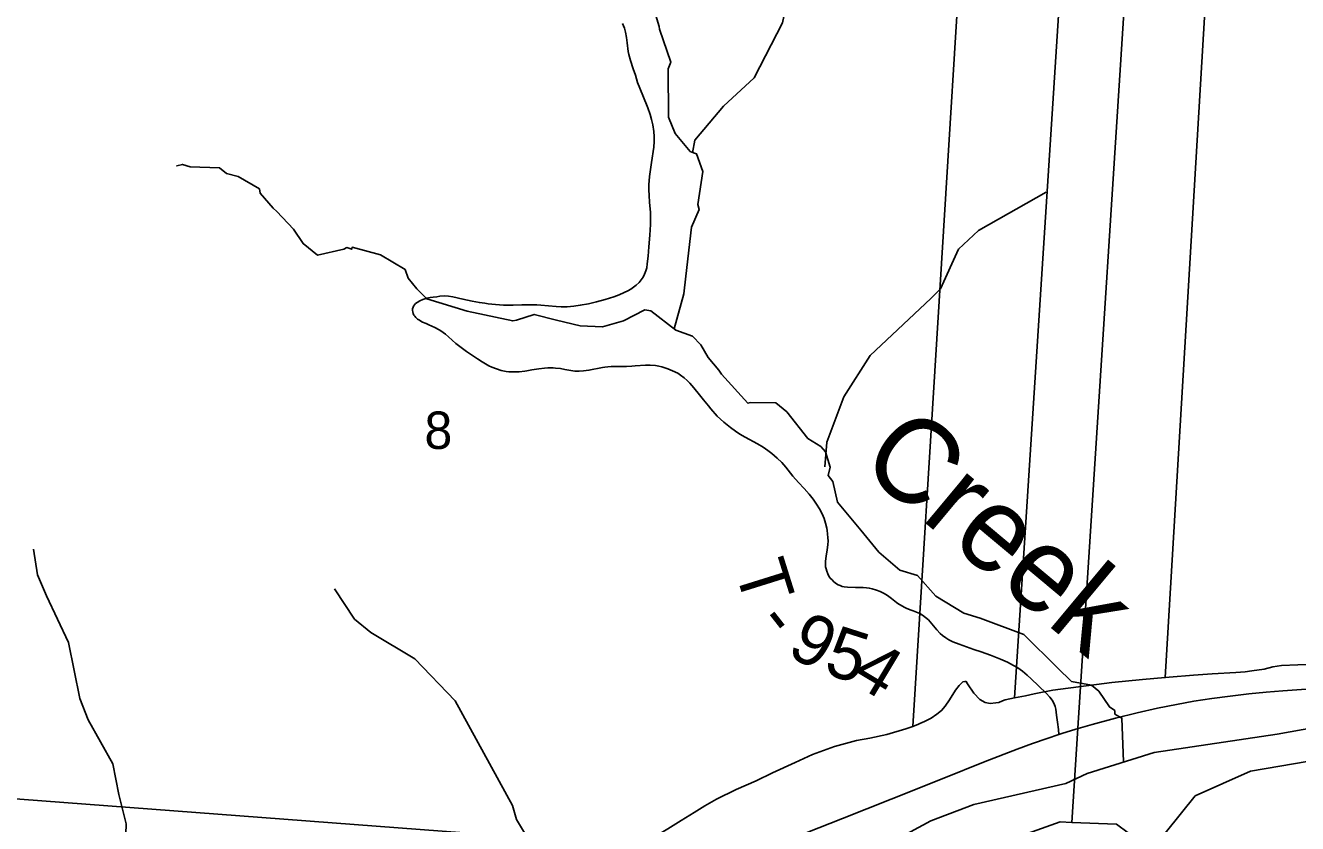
# Model space of a CAD drawing. Extents: x 0 to 34, y 0 to 22.
# Drawn here: x 27.11 to 28.533, y 15.294 to 16.186 of the extents above; entities that cross this region are included whole.
import ezdxf

# ---------------------------------------------------------------- set-up
doc = ezdxf.new("R2010")
doc.units = 0
for name, color, linetype in [('GM_X_County_Text', 7, 'Continuous'), ('GM_X_Major_River', 7, 'Continuous'), ('GM_X_Minor_River', 7, 'Continuous'), ('GM_X_Minor_River_Text', 7, 'Continuous'), ('GM_X_Section', 7, 'Continuous'), ('GM_X_Section_Text', 7, 'Continuous'), ('GM_X_State_Route', 7, 'Continuous'), ('GM_X_Township_Road', 7, 'Continuous'), ('GM_X_Township_Road_Text', 7, 'Continuous'), ('SH_Cut_Line', 7, 'Continuous')]:
    doc.layers.add(name, color=color, linetype=linetype)

msp = doc.modelspace()

# ---------------------------------------------------------------- linework, layer by layer
at = {"layer": 'GM_X_County_Text'}
for points in [[(27.0716, 14.2873), (27.1862, 14.3829), (27.4012, 14.5633), (27.5003, 14.6738), (27.528, 14.7368), (27.5892, 14.8006), (27.6689, 14.9115), (27.8265, 15.0679), (27.967, 15.1616), (28.1376, 15.2493), (28.2671, 15.2953), (28.2799, 15.2948), (28.2867, 15.4004), (28.3527, 16.4269), (28.3944, 17.0528), (28.4159, 17.3358), (28.4427, 17.7695)], [(28.4427, 17.7695), (28.4159, 17.3358), (28.3944, 17.0528), (28.3527, 16.4269), (28.2867, 15.4004), (28.2799, 15.2948), (28.3301, 15.293), (28.3692, 15.2637), (28.4182, 15.3245), (28.4801, 15.3522), (28.6571, 15.3822), (28.9104, 15.3867), (29.0987, 15.3975), (29.1238, 15.3963), (29.3286, 15.3596), (29.3112, 15.3354), (29.211, 15.3094), (29.213, 15.295), (29.3097, 15.2479), (29.423, 15.2518), (29.4264, 15.2648), (29.4018, 15.2725), (29.4304, 15.2876), (29.5713, 15.2568)]]:
    msp.add_lwpolyline(points, dxfattribs=at)
at = {"layer": 'GM_X_Major_River'}
msp.add_line((28.3722, 15.373), (28.2973, 15.3494), dxfattribs=at)
for points in [[(29.1018, 15.4118), (28.9867, 15.4094), (28.927, 15.4195), (28.9024, 15.4184), (28.7152, 15.4124), (28.568, 15.4039), (28.5098, 15.3936), (28.3722, 15.373)], [(28.2973, 15.3494), (28.2735, 15.3383), (28.1706, 15.3147), (28.1223, 15.2965), (28.072, 15.2695)]]:
    msp.add_lwpolyline(points, dxfattribs=at)
at = {"layer": 'GM_X_Minor_River'}
for points in [[(27.8558, 16.0439), (27.8582, 16.0579), (27.8903, 16.096), (27.9249, 16.1279), (27.9566, 16.1892), (27.9633, 16.2213), (27.9793, 16.2754), (27.9853, 16.3121), (27.9977, 16.3333), (28.0012, 16.3389)], [(27.8354, 15.847), (27.8462, 15.8863), (27.8481, 15.906), (27.8548, 15.9608), (27.8631, 15.9806), (27.8616, 15.9859), (27.8672, 16.0231), (27.8604, 16.0429), (27.857, 16.044), (27.8532, 16.0452), (27.8362, 16.0653), (27.829, 16.0839), (27.8286, 16.1378), (27.8316, 16.1454), (27.8187, 16.1823), (27.8183, 16.1853), (27.8149, 16.1975)], [(27.8025, 15.8684), (27.7785, 15.8561), (27.7551, 15.8492), (27.7302, 15.8503), (27.7037, 15.8567), (27.6787, 15.8631), (27.6587, 15.8566), (27.6546, 15.8558), (27.6035, 15.8667), (27.5585, 15.8807), (27.5472, 15.8917), (27.5377, 15.9038), (27.5343, 15.9133), (27.5067, 15.9296), (27.4749, 15.9383), (27.4745, 15.936), (27.4689, 15.9379), (27.4658, 15.936), (27.4364, 15.9294), (27.4201, 15.9423), (27.4095, 15.9586), (27.3906, 15.9783), (27.3868, 15.9821), (27.372, 15.9988), (27.3713, 16.0034), (27.3475, 16.0174), (27.3346, 16.0208), (27.3267, 16.0272), (27.2938, 16.0283), (27.2851, 16.0309), (27.279, 16.0294), (27.2786, 16.0294)], [(28.0036, 15.6925), (28.0059, 15.7202), (28.0251, 15.7708), (28.0545, 15.8172), (28.1223, 15.8808), (28.1333, 15.8918), (28.1533, 15.936), (28.1756, 15.9569), (28.2513, 16)], [(27.8651, 15.8291), (27.8557, 15.8388), (27.8371, 15.8456), (27.8092, 15.8672), (27.8024, 15.8684)], [(28.3377, 15.3625), (28.3361, 15.4116), (28.3282, 15.4161), (28.3282, 15.4199), (28.3222, 15.4241), (28.3104, 15.4416), (28.3021, 15.4484), (28.2798, 15.4525), (28.2639, 15.4677), (28.2264, 15.5052), (28.1777, 15.5233), (28.1591, 15.529), (28.1281, 15.5479), (28.1073, 15.5711), (28.0876, 15.5771), (28.085, 15.5794), (28.0642, 15.5972), (28.0441, 15.6219), (28.018, 15.653), (28.0127, 15.6761), (28.0074, 15.683), (28.0097, 15.6921), (28.0044, 15.7092), (27.9994, 15.7152), (27.9847, 15.7243), (27.9612, 15.7543), (27.9491, 15.7641), (27.9208, 15.7645), (27.9177, 15.7637), (27.8882, 15.7963), (27.8852, 15.8009), (27.8731, 15.8149), (27.865, 15.8292)], [(27.1708, 15.1045), (27.1625, 15.1324), (27.1653, 15.1597), (27.1982, 15.2243), (27.2153, 15.2508), (27.2215, 15.2699), (27.2222, 15.2931), (27.2141, 15.326), (27.2073, 15.3604), (27.1796, 15.4095), (27.1705, 15.4333), (27.1577, 15.496), (27.1332, 15.5484), (27.123, 15.5719), (27.1185, 15.6005)], [(27.8078, 15.0936), (27.775, 15.1224), (27.7579, 15.1446), (27.7366, 15.1806), (27.6794, 15.2637), (27.6589, 15.2981), (27.6545, 15.3138), (27.5904, 15.4309), (27.545, 15.4779), (27.496, 15.5072), (27.4775, 15.5222), (27.4551, 15.556)]]:
    msp.add_lwpolyline(points, dxfattribs=at)
at = {"layer": 'GM_X_Section'}
for points in [[(27.1082, 16.21), (27.1198, 16.4014), (27.6098, 16.3785), (28.1612, 16.354), (28.1022, 15.4021), (28.0942, 15.3994), (28.073, 15.3933), (28.0541, 15.3891), (28.0393, 15.3864), (28.0147, 15.3799), (27.9901, 15.3708), (27.9704, 15.362), (27.9454, 15.3502), (27.9269, 15.3415), (27.9046, 15.3316), (27.8826, 15.3209), (27.8697, 15.3133), (27.8576, 15.3061), (27.8429, 15.297), (27.8281, 15.2875), (27.8077, 15.2753), (27.7994, 15.27), (27.7971, 15.2681), (27.0537, 15.3245)], [(28.2749, 16.348), (28.216, 15.4343), (28.2056, 15.4319), (28.2025, 15.4307), (28.1984, 15.4288), (28.195, 15.4285), (28.1889, 15.4277), (28.1832, 15.4288), (28.1772, 15.4322), (28.1703, 15.4394), (28.1635, 15.45), (28.162, 15.4523), (28.1604, 15.4523), (28.1582, 15.4519), (28.154, 15.4481), (28.1499, 15.4428), (28.1431, 15.4318), (28.1385, 15.4249), (28.1344, 15.42), (28.1291, 15.4158), (28.1226, 15.4116), (28.1151, 15.4078), (28.1102, 15.4055), (28.1086, 15.4048), (28.1022, 15.4021), (28.1612, 16.354)]]:
    msp.add_lwpolyline(points, dxfattribs=at)
for points in [[(28.2749, 16.348), (28.4372, 16.34), (28.3846, 15.4569), (28.359, 15.4546), (28.3249, 15.4515), (28.259, 15.4426), (28.2381, 15.4388), (28.2283, 15.4365), (28.216, 15.4343)], [(28.4372, 16.34), (28.6263, 16.3303), (28.572, 15.4729), (28.5552, 15.472), (28.5329, 15.4712), (28.5147, 15.4704), (28.5048, 15.4689), (28.4954, 15.4662), (28.4813, 15.4643), (28.4741, 15.4632), (28.4635, 15.4627), (28.437, 15.4612), (28.4162, 15.4596), (28.3889, 15.4573), (28.3846, 15.4569)], [(27.0537, 15.3245), (27.7971, 15.2681), (27.7884, 15.2624), (27.7785, 15.2559), (27.771, 15.251), (27.7619, 15.2445), (27.743, 15.2331), (27.7146, 15.2152), (27.6987, 15.2038), (27.6828, 15.1924), (27.6624, 15.1753), (27.656, 15.1697), (27.6401, 15.159), (27.6276, 15.1491), (27.6174, 15.1393), (27.6042, 15.1237), (27.597, 15.1172), (27.5777, 15.1036), (27.5644, 15.0941), (27.5553, 15.0864), (27.0368, 15.114)]]:
    msp.add_lwpolyline(points, close=True, dxfattribs=at)
at = {"layer": 'GM_X_State_Route'}
for points in [[(28.287, 15.3999), (28.3027, 15.4045), (28.3291, 15.4116), (28.3531, 15.4174), (28.376, 15.4225), (28.397, 15.4267), (28.4166, 15.4303), (28.4366, 15.4335), (28.4573, 15.4362), (28.4781, 15.4387), (28.4976, 15.4406), (28.5162, 15.4422), (28.537, 15.4436), (28.557, 15.4446), (28.5853, 15.4453), (28.6357, 15.4462), (28.6794, 15.4468), (28.7148, 15.4473), (28.7545, 15.4479), (28.7905, 15.4484)], [(28.2657, 15.3931), (28.2689, 15.3942), (28.2846, 15.3992), (28.287, 15.3999)], [(27.7444, 15.1883), (27.7503, 15.1906), (27.7883, 15.2059), (27.8178, 15.2176), (27.8385, 15.2259), (27.861, 15.2348), (27.9194, 15.2582), (27.9513, 15.2704), (27.983, 15.283), (28.0236, 15.2993), (28.0779, 15.321), (28.1349, 15.3435), (28.1831, 15.3628), (28.219, 15.3769), (28.2361, 15.383), (28.2523, 15.3887), (28.2657, 15.3931)]]:
    msp.add_lwpolyline(points, dxfattribs=at)
at = {"layer": 'GM_X_Township_Road'}
msp.add_lwpolyline([(28.2657, 15.3931), (28.265, 15.3987), (28.264, 15.4071), (28.263, 15.4147), (28.2621, 15.4215), (28.2614, 15.4246), (28.26, 15.4281), (28.2581, 15.4314), (28.2554, 15.4349), (28.2512, 15.4395), (28.2346, 15.4555), (28.23, 15.4597), (28.2247, 15.464), (28.2196, 15.4676), (28.2148, 15.4705), (28.2081, 15.4739), (28.2001, 15.4774), (28.1891, 15.4818), (28.1786, 15.4856), (28.1704, 15.4884), (28.154, 15.4942), (28.1471, 15.4969), (28.1426, 15.499), (28.139, 15.5012), (28.1355, 15.5038), (28.1328, 15.5063), (28.1291, 15.5104), (28.1236, 15.5171), (28.1198, 15.5213), (28.1165, 15.5242), (28.113, 15.5268), (28.1102, 15.5284), (28.1062, 15.5301), (28.1027, 15.5314), (28.0992, 15.5326), (28.0947, 15.5345), (28.0925, 15.5357), (28.0882, 15.5381), (28.0867, 15.539), (28.0841, 15.5407), (28.0782, 15.5453), (28.0737, 15.5486), (28.07, 15.5509), (28.0655, 15.5531), (28.0614, 15.5547), (28.0566, 15.5561), (28.0535, 15.5569), (28.0502, 15.5573), (28.0466, 15.5575), (28.0379, 15.5577), (28.0292, 15.5578), (28.0255, 15.5583), (28.0233, 15.5588), (28.0209, 15.5597), (28.0188, 15.5607), (28.017, 15.5618), (28.014, 15.564), (28.0119, 15.5661), (28.0099, 15.5682), (28.0084, 15.5702), (28.007, 15.5728), (28.006, 15.5757), (28.0051, 15.5784), (28.0047, 15.5806), (28.0045, 15.583), (28.0047, 15.5871), (28.0052, 15.5926), (28.0063, 15.5999), (28.0071, 15.6055), (28.0074, 15.6099), (28.0072, 15.613), (28.0069, 15.6178), (28.0064, 15.6215), (28.006, 15.624), (28.0047, 15.6294), (28.0029, 15.6348), (28.0007, 15.64), (27.9979, 15.6456), (27.9946, 15.6509), (27.9907, 15.6565), (27.9864, 15.6619), (27.9807, 15.6684), (27.9743, 15.6752), (27.9681, 15.6822), (27.96, 15.6924), (27.9555, 15.6975), (27.9506, 15.7024), (27.9446, 15.7075), (27.9401, 15.7109), (27.9347, 15.7145), (27.9284, 15.7183), (27.9147, 15.7256), (27.9088, 15.729), (27.9037, 15.7324), (27.8983, 15.7366), (27.8909, 15.7424), (27.8834, 15.7493), (27.8763, 15.7574), (27.8735, 15.7607), (27.868, 15.7674), (27.8634, 15.7732), (27.8573, 15.781), (27.8528, 15.7863), (27.8496, 15.7892), (27.8464, 15.7921), (27.8422, 15.7951), (27.8392, 15.7972), (27.8335, 15.8001), (27.828, 15.8024), (27.8249, 15.8035), (27.8215, 15.8044), (27.8181, 15.8052), (27.8143, 15.8058), (27.8083, 15.8062), (27.8031, 15.8062), (27.7917, 15.8054), (27.788, 15.8052), (27.7818, 15.805), (27.7738, 15.8048), (27.7686, 15.8049), (27.7648, 15.8048), (27.7609, 15.8044), (27.7578, 15.804), (27.7552, 15.8036), (27.7399, 15.8006), (27.7338, 15.7998), (27.7289, 15.7996), (27.724, 15.7997), (27.7197, 15.8002), (27.7131, 15.8015), (27.7082, 15.8025), (27.7026, 15.8031), (27.6999, 15.8034), (27.697, 15.8034), (27.6939, 15.8033), (27.6902, 15.8031), (27.684, 15.8024), (27.676, 15.801), (27.6705, 15.8), (27.6681, 15.7996), (27.6619, 15.7989), (27.6582, 15.7987), (27.6527, 15.7988), (27.6504, 15.7989), (27.6472, 15.7994), (27.6418, 15.8005), (27.6364, 15.8021), (27.6313, 15.8041), (27.628, 15.8057), (27.6205, 15.8101), (27.6153, 15.8134), (27.6029, 15.8216), (27.5954, 15.8271), (27.591, 15.8305), (27.5828, 15.8381), (27.5794, 15.8409), (27.5743, 15.8446), (27.5722, 15.8459), (27.5674, 15.8485), (27.5642, 15.85), (27.5609, 15.8515), (27.5577, 15.8529), (27.5539, 15.8546), (27.5519, 15.8557), (27.5502, 15.8568), (27.5483, 15.8579), (27.5463, 15.8595), (27.5451, 15.861), (27.5442, 15.8624), (27.5434, 15.8641), (27.5429, 15.8659), (27.5426, 15.8674), (27.5426, 15.8692), (27.5431, 15.8712), (27.5436, 15.8724), (27.5448, 15.8739), (27.546, 15.8753), (27.5478, 15.8766), (27.5506, 15.8782), (27.5541, 15.8797), (27.5565, 15.8805), (27.5586, 15.8812), (27.5624, 15.882), (27.5658, 15.8824), (27.5697, 15.8829), (27.573, 15.8834), (27.5785, 15.8837), (27.5827, 15.8835), (27.5876, 15.8827), (27.599, 15.8802), (27.6093, 15.8779), (27.6173, 15.8764), (27.6234, 15.8755), (27.6271, 15.875), (27.6352, 15.8742), (27.6445, 15.8736), (27.655, 15.8734), (27.665, 15.8737), (27.6724, 15.8738), (27.6817, 15.8737), (27.6861, 15.8735), (27.7034, 15.872), (27.709, 15.8717), (27.7154, 15.8716), (27.7229, 15.8724), (27.7301, 15.8734), (27.7393, 15.8751), (27.7484, 15.8772), (27.758, 15.8798), (27.7676, 15.8826), (27.7738, 15.8849), (27.7793, 15.8875), (27.7835, 15.8896), (27.7867, 15.8914), (27.7898, 15.8935), (27.7927, 15.8957), (27.7959, 15.8987), (27.7982, 15.9016), (27.8004, 15.9048), (27.8021, 15.9081), (27.8035, 15.9117), (27.8045, 15.9153), (27.8052, 15.9196), (27.806, 15.9283), (27.807, 15.9388), (27.8081, 15.9516), (27.8088, 15.9636), (27.8088, 15.9705), (27.8086, 15.9771), (27.8075, 15.9888), (27.8071, 15.9962), (27.8069, 16.0023), (27.807, 16.0079), (27.8077, 16.0174), (27.8088, 16.0253), (27.8099, 16.0329), (27.8124, 16.0502), (27.8129, 16.0564), (27.8129, 16.062), (27.8124, 16.0676), (27.8113, 16.0751), (27.81, 16.0812), (27.8084, 16.0866), (27.8056, 16.0942), (27.8002, 16.1081), (27.7944, 16.1226), (27.7918, 16.1306), (27.7893, 16.1379), (27.7863, 16.147), (27.7844, 16.1539), (27.7838, 16.1572), (27.7826, 16.167), (27.7818, 16.1729), (27.7807, 16.1787), (27.7796, 16.1832), (27.7775, 16.1887)], dxfattribs=at)
at = {"layer": 'SH_Cut_Line'}
for points in [[(28.3692, 15.2637), (28.4182, 15.3245), (28.4801, 15.3522), (28.6571, 15.3822), (28.9104, 15.3867), (29.0987, 15.3975), (29.1238, 15.3963), (29.3286, 15.3596), (29.3112, 15.3354), (29.211, 15.3094), (29.213, 15.295), (29.3097, 15.2479)], [(28.1376, 15.2493), (28.2671, 15.2953), (28.2799, 15.2948), (28.3301, 15.293)]]:
    msp.add_lwpolyline(points, dxfattribs=at)

# ---------------------------------------------------------------- texts
at = {"layer": 'GM_X_Minor_River_Text'}
msp.add_text('Creek', height=0.09469, rotation=320.1349, dxfattribs=at).set_placement((28.0395, 15.6936))
at = {"layer": 'GM_X_Section_Text'}
msp.add_text('8', height=0.0419, rotation=0, dxfattribs=at).set_placement((27.5559, 15.7126))
at = {"layer": 'GM_X_Township_Road_Text'}
for s, rotation, p in [('T', 287.3731, (27.9025, 15.578)), ('-', 308.0893, (27.9255, 15.5177)), ('9', 331.8752, (27.9595, 15.483)), ('5', 342.2489, (28.0007, 15.4621)), ('4', 329.0438, (28.0309, 15.4528))]:
    msp.add_text(s, height=0.0568, rotation=rotation, dxfattribs=at).set_placement(p)

doc.saveas('drawing.dxf')
